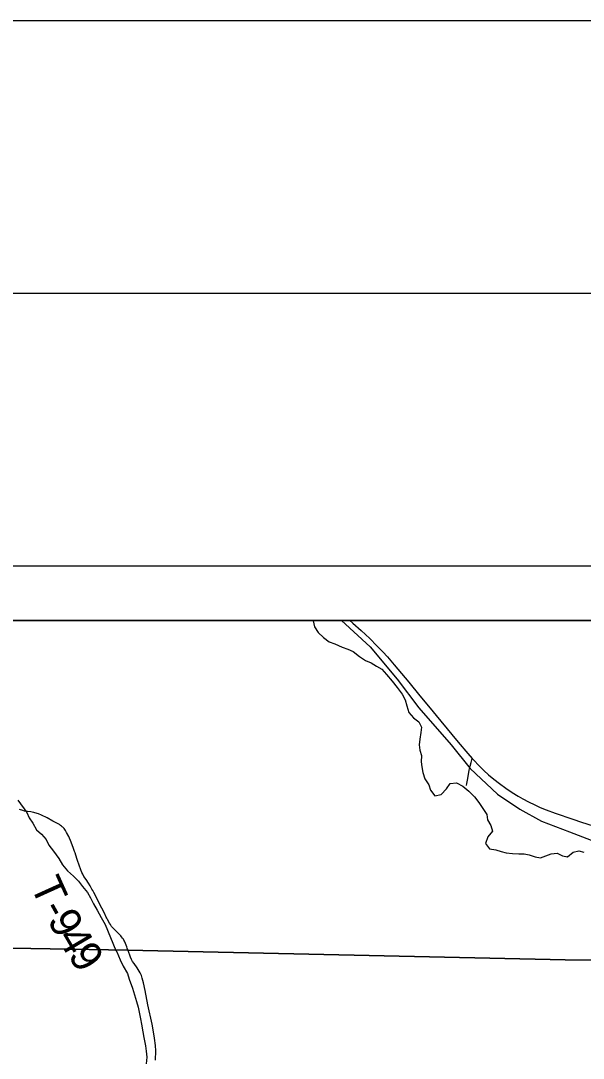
# Model space of a CAD drawing. Extents: x 0 to 34, y 0 to 22.
# Drawn here: x 25.254 to 26.286, y 20.097 to 22 of the extents above; entities that cross this region are included whole.
import ezdxf

# ---------------------------------------------------------------- set-up
doc = ezdxf.new("R2010")
doc.units = 0
for name, color, linetype in [('GM_X_Corporation', 7, 'Continuous'), ('GM_X_Minor_River', 7, 'Continuous'), ('GM_X_Rail_Line', 7, 'Continuous'), ('GM_X_State_Route', 7, 'Continuous'), ('GM_X_Township_Road', 7, 'Continuous'), ('GM_X_Township_Road_Text', 7, 'Continuous'), ('SH_Border', 7, 'Continuous'), ('SH_Cut_Line', 7, 'Continuous'), ('SH_Data', 7, 'Continuous')]:
    doc.layers.add(name, color=color, linetype=linetype)

msp = doc.modelspace()

# ---------------------------------------------------------------- linework, layer by layer
at = {"layer": 'GM_X_Corporation'}
msp.add_lwpolyline([(27.1022, 20.9), (23.5167, 20.9), (23.5167, 20.3276), (24.0328, 20.3169), (24.0688, 20.3165), (24.5249, 20.3107), (25.4507, 20.2949), (26.2533, 20.2773), (26.5702, 20.276), (26.6351, 20.2734), (26.7196, 20.2707), (26.7822, 20.2704), (27.0031, 20.2673), (27.0873, 20.2665), (27.089, 20.3692), (27.0897, 20.4135), (27.0898, 20.417)], close=True, dxfattribs=at)
msp.add_lwpolyline([(27.1022, 20.9), (23.5167, 20.9), (23.5167, 20.3276), (24.0328, 20.3169), (24.0688, 20.3165), (24.5249, 20.3107), (25.4507, 20.2949), (26.2533, 20.2773), (26.5702, 20.276), (26.6351, 20.2734), (26.7196, 20.2707), (26.7822, 20.2704), (27.0031, 20.2673), (27.0873, 20.2665), (27.089, 20.3692), (27.0897, 20.4135), (27.0898, 20.417)], close=True, dxfattribs=at)
msp.add_lwpolyline([(27.0234, 16.6611), (27.0349, 17.5522), (27.0419, 17.8236), (27.0487, 18.5805), (27.0719, 19.3912), (27.0733, 19.498), (27.0761, 19.6806), (27.0864, 20.0138), (27.0885, 20.1139), (27.0907, 20.123), (27.0873, 20.2665), (27.0031, 20.2673), (26.7822, 20.2704), (26.7196, 20.2707), (26.6351, 20.2734), (26.5702, 20.276), (26.2533, 20.2773), (25.4507, 20.2949), (24.5249, 20.3107), (24.0688, 20.3165), (24.0328, 20.3169), (23.5167, 20.3276), (23.5167, 14.5642)], dxfattribs=at)
msp.add_lwpolyline([(27.0234, 16.6611), (27.0349, 17.5522), (27.0419, 17.8236), (27.0487, 18.5805), (27.0719, 19.3912), (27.0733, 19.498), (27.0761, 19.6806), (27.0864, 20.0138), (27.0885, 20.1139), (27.0907, 20.123), (27.0873, 20.2665), (27.0031, 20.2673), (26.7822, 20.2704), (26.7196, 20.2707), (26.6351, 20.2734), (26.5702, 20.276), (26.2533, 20.2773), (25.4507, 20.2949), (24.5249, 20.3107), (24.0688, 20.3165), (24.0328, 20.3169), (23.5167, 20.3276), (23.5167, 14.5642)], dxfattribs=at)
at = {"layer": 'GM_X_Minor_River'}
for points in [[(25.7901, 20.9), (25.7905, 20.8991), (25.7933, 20.8882), (25.7998, 20.878), (25.8098, 20.8686), (25.8201, 20.8608), (25.8307, 20.8571), (25.844, 20.8512), (25.8546, 20.8472), (25.8641, 20.8427), (25.876, 20.8338), (25.8866, 20.8263), (25.8973, 20.8223), (25.9068, 20.8163), (25.9167, 20.8104), (25.9255, 20.8006), (25.9358, 20.7886), (25.945, 20.777), (25.9542, 20.7649), (25.9596, 20.7544), (25.9628, 20.743), (25.9663, 20.7309), (25.9747, 20.7212), (25.9846, 20.7141), (25.9893, 20.7043), (25.9886, 20.6944), (25.9868, 20.6822)], [(25.9868, 20.6822), (25.9854, 20.672), (25.9867, 20.6618), (25.9898, 20.6519), (25.9892, 20.6405), (25.99, 20.6311), (25.992, 20.6212), (25.9959, 20.6095), (26.0028, 20.5986), (26.0063, 20.5884), (26.014, 20.5782), (26.0257, 20.5807), (26.0354, 20.591), (26.0422, 20.601), (26.0535, 20.6019), (26.0657, 20.5959), (26.0767, 20.587), (26.0871, 20.5761), (26.0951, 20.566), (26.1097, 20.5441), (26.1109, 20.5339), (26.1167, 20.5237), (26.1199, 20.5135), (26.1116, 20.5028), (26.1072, 20.491), (26.1141, 20.4812), (26.1259, 20.4794), (26.1357, 20.4758), (26.1452, 20.4736), (26.1566, 20.4722), (26.168, 20.472), (26.1778, 20.4721), (26.1873, 20.4699), (26.1983, 20.4663), (26.2078, 20.4645), (26.2176, 20.468), (26.2277, 20.4716), (26.2383, 20.4728), (26.2482, 20.468), (26.2577, 20.4666), (26.2566, 20.4666)], [(25.2489, 20.5703), (25.2654, 20.5478), (25.2693, 20.5376), (25.2762, 20.5278), (25.2828, 20.5161), (25.2923, 20.5079), (25.3004, 20.4981), (25.3058, 20.4879), (25.3138, 20.4766), (25.3238, 20.4631), (25.3307, 20.4518), (25.3399, 20.4405), (25.3506, 20.4308), (25.3602, 20.4214), (25.3675, 20.4117), (25.3763, 20.4011), (25.382, 20.391), (25.3878, 20.38), (25.3944, 20.3683), (25.4017, 20.3552), (25.4087, 20.342), (25.4288, 20.2946), (25.4304, 20.2918)], [(26.2577, 20.4666), (26.2677, 20.4746), (26.2783, 20.4771), (26.2878, 20.4749)], [(25.4304, 20.2918), (25.4364, 20.2775), (25.4418, 20.2657), (25.4502, 20.2521), (25.4532, 20.2422), (25.459, 20.2252), (25.4628, 20.2134), (25.4666, 20.2009), (25.4697, 20.1906), (25.4735, 20.1694), (25.4754, 20.1591), (25.4781, 20.1451), (25.48, 20.1352), (25.4827, 20.1196), (25.4839, 20.1101), (25.4851, 20.0991), (25.4843, 20.0866)]]:
    msp.add_lwpolyline(points, dxfattribs=at)
at = {"layer": 'GM_X_Rail_Line'}
msp.add_lwpolyline([(25.8427, 20.9), (25.8951, 20.8513), (25.9452, 20.7924), (25.9846, 20.7394), (26.0443, 20.6716), (26.079, 20.6285), (26.1292, 20.5813), (26.1698, 20.5536), (26.2096, 20.5318), (26.261, 20.5119), (26.3755, 20.4679), (26.481, 20.4259), (26.544, 20.3901), (26.5981, 20.3494), (26.6515, 20.2982), (26.6765, 20.2746)], dxfattribs=at)
at = {"layer": 'GM_X_State_Route'}
for points in [[(25.8578, 20.9), (25.8635, 20.8952), (25.8787, 20.8815), (25.8946, 20.8666), (25.9078, 20.8535), (25.9186, 20.8424), (25.9269, 20.8332), (25.9395, 20.8186), (25.9662, 20.7867), (25.9865, 20.7619)], [(25.9865, 20.7619), (26.0024, 20.7425), (26.0249, 20.7151), (26.0567, 20.6769), (26.0744, 20.6561), (26.0826, 20.6469), (26.0856, 20.6436), (26.0951, 20.6337), (26.1039, 20.6249), (26.1127, 20.617), (26.1222, 20.6089), (26.1325, 20.6009), (26.1442, 20.5925), (26.156, 20.5845), (26.1671, 20.5776), (26.1758, 20.5726), (26.1862, 20.5671), (26.1974, 20.5615), (26.2076, 20.5569), (26.2186, 20.5525), (26.2349, 20.5464), (26.2672, 20.5353), (26.2831, 20.5299), (26.3359, 20.5133)]]:
    msp.add_lwpolyline(points, dxfattribs=at)
at = {"layer": 'GM_X_Township_Road'}
for points in [[(26.072, 20.5971), (26.0729, 20.6008), (26.0748, 20.6099), (26.0773, 20.6252), (26.0788, 20.6326), (26.0806, 20.6392), (26.0826, 20.6469)], [(25.4509, 20.2944), (25.4496, 20.2988), (25.4489, 20.301), (25.4476, 20.3043), (25.4464, 20.3073), (25.4442, 20.3118), (25.4432, 20.3134), (25.4423, 20.315), (25.4407, 20.3172), (25.439, 20.3195), (25.4374, 20.3213), (25.4357, 20.3232), (25.4305, 20.3286), (25.4257, 20.3334), (25.4243, 20.3349), (25.4226, 20.3366), (25.4208, 20.3388), (25.4185, 20.3423), (25.4168, 20.3449), (25.4133, 20.3515), (25.4121, 20.3537), (25.411, 20.3558), (25.4074, 20.3629), (25.3981, 20.3812), (25.3903, 20.3966), (25.388, 20.4009), (25.386, 20.4047), (25.3846, 20.4073), (25.3825, 20.4109), (25.3813, 20.413), (25.3782, 20.418), (25.3739, 20.4245), (25.37, 20.4304), (25.3677, 20.4347), (25.3663, 20.4374), (25.3641, 20.4423), (25.3581, 20.4596), (25.3568, 20.4635), (25.3538, 20.4734), (25.3528, 20.4763), (25.351, 20.4815), (25.3466, 20.4931), (25.3422, 20.5034), (25.3382, 20.5111), (25.336, 20.5149), (25.3334, 20.5183), (25.3325, 20.5195), (25.3313, 20.5206), (25.3301, 20.5216), (25.3289, 20.5226), (25.3269, 20.524), (25.3248, 20.5254), (25.3128, 20.5319), (25.3025, 20.5376), (25.2919, 20.5429), (25.2868, 20.5451), (25.2842, 20.546), (25.2821, 20.5467), (25.28, 20.5473), (25.2779, 20.5477), (25.275, 20.5483), (25.2724, 20.5487), (25.2662, 20.5493), (25.2607, 20.5503), (25.2577, 20.551), (25.2518, 20.5529)], [(25.5013, 20.0935), (25.5021, 20.1102), (25.5011, 20.1201), (25.4993, 20.1335), (25.4963, 20.1527), (25.4951, 20.1594), (25.4874, 20.1946), (25.4824, 20.2213), (25.4793, 20.2352), (25.477, 20.2438), (25.4754, 20.2488), (25.4731, 20.2538), (25.4676, 20.2624), (25.4619, 20.2705), (25.4592, 20.2746), (25.4573, 20.2782), (25.4557, 20.2821), (25.4509, 20.2944)]]:
    msp.add_lwpolyline(points, dxfattribs=at)
at = {"layer": 'SH_Border'}
msp.add_lwpolyline([(1.5, 21.5), (33.5, 21.5), (33.5, 0.5), (1.5, 0.5)], close=True, dxfattribs=at)
at = {"layer": 'SH_Cut_Line'}
msp.add_lwpolyline([(0, 0), (34, 0), (34, 22), (0, 22)], close=True, dxfattribs=at)
at = {"layer": 'SH_Data'}
for points in [[(23.4167, 21), (30.4167, 21), (30.4167, 14), (23.4167, 14)], [(23.5167, 20.9), (30.3167, 20.9), (30.3167, 14.1), (23.5167, 14.1)]]:
    msp.add_lwpolyline(points, close=True, dxfattribs=at)

# ---------------------------------------------------------------- texts
at = {"layer": 'GM_X_Township_Road_Text'}
for s, rotation, p in [('T', 294.3681, (25.2708, 20.4142)), ('9', 298.9303, (25.3019, 20.3506)), ('-', 299.0461, (25.2906, 20.3709)), ('4', 300.5098, (25.3197, 20.3185)), ('9', 303.6567, (25.3393, 20.2854))]:
    msp.add_text(s, height=0.0568, rotation=rotation, dxfattribs=at).set_placement(p)

doc.saveas('drawing.dxf')
